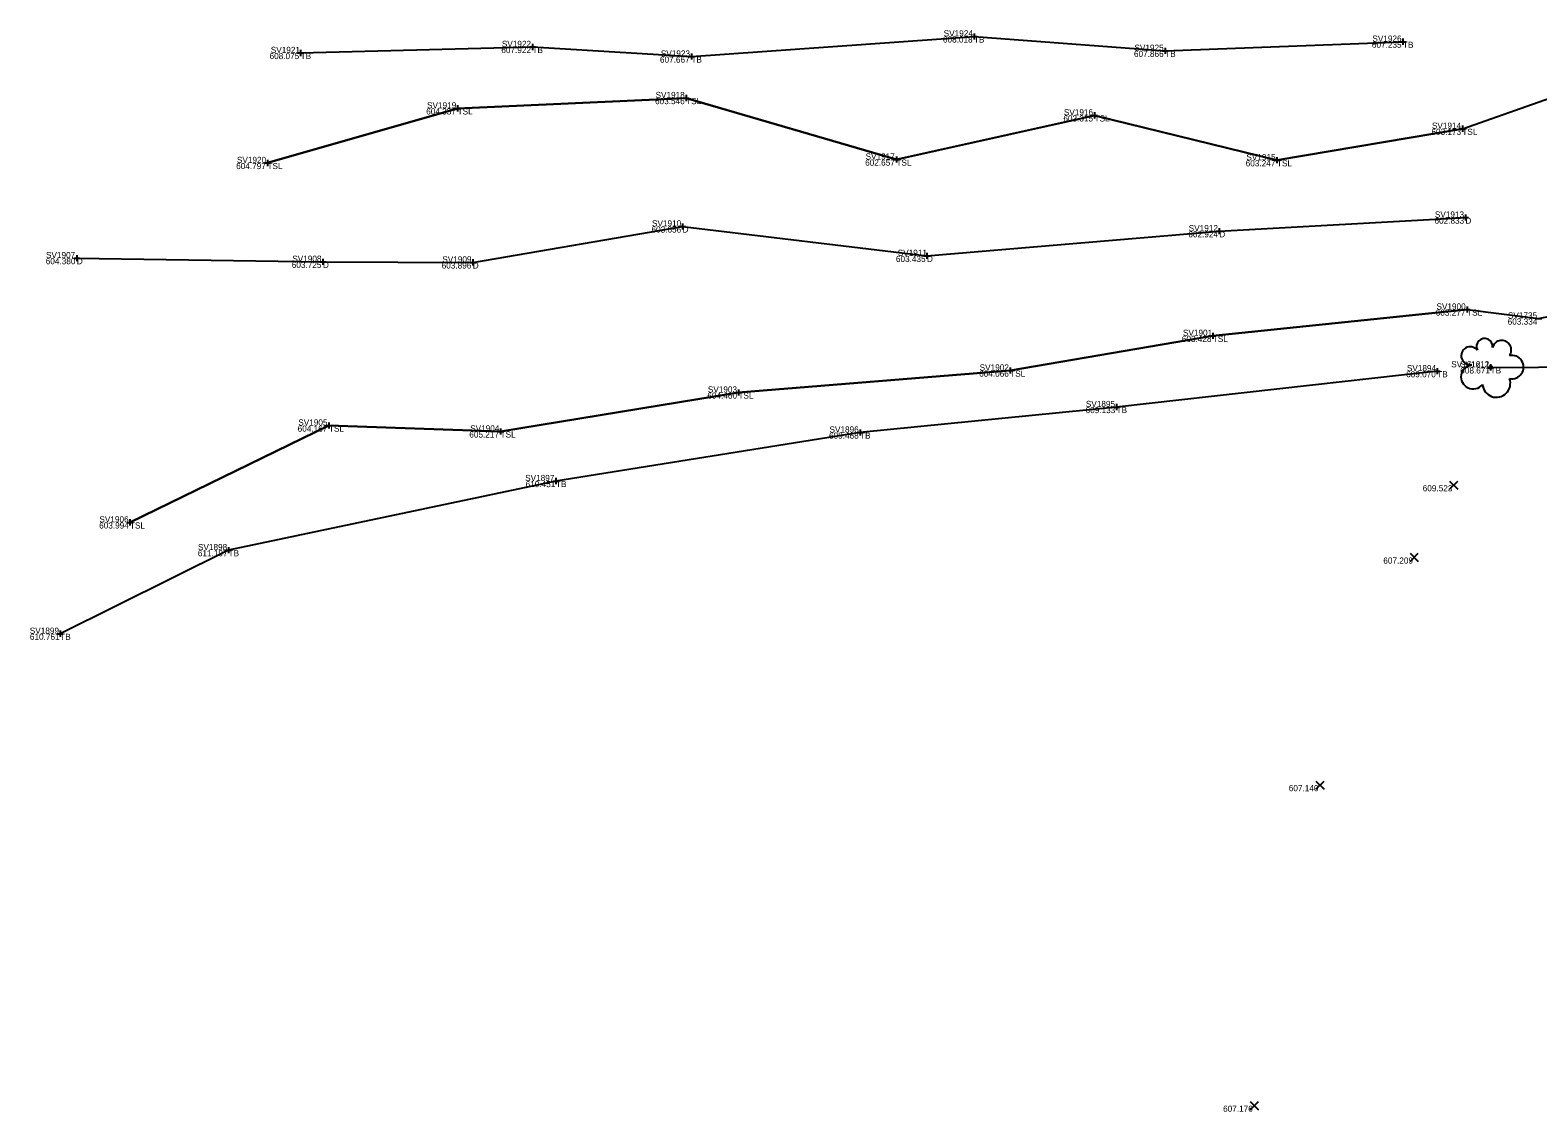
# Model space of a CAD drawing. Extents: x -2 to 1979875, y -2 to 232027.
# Drawn here: x 1978304.6 to 1978427.5, y 231237.5 to 231325.6 of the extents above; entities that cross this region are included whole.
import ezdxf

# ---------------------------------------------------------------- set-up
doc = ezdxf.new("R2010")
doc.units = 0
for name, color, linetype in [('_CIVIL_CONSTRUCTION', 7, 'Continuous'), ('DR_X_Ditch', 7, 'Continuous'), ('GE_X_Alignment', 7, 'Continuous'), ('GE_X_Alignment_100_Curve_Data', 7, 'Continuous'), ('GE_X_Alignment_100_Stations', 7, 'Continuous'), ('HY_X_Water_Edge', 7, 'Continuous'), ('SV_X_Random_Point', 7, 'Continuous'), ('SV_X_Toe_of_Slope', 7, 'Continuous'), ('SV_X_Top_of_Bank', 7, 'Continuous'), ('VG_X_Cells', 7, 'Continuous')]:
    doc.layers.add(name, color=color, linetype=linetype)

msp = doc.modelspace()

# ---------------------------------------------------------------- linework, layer by layer
at = {"layer": 'DR_X_Ditch'}
msp.add_lwpolyline([(1978308.45, 231307), (1978328.5, 231306.7), (1978340.7, 231306.65), (1978357.79, 231309.58), (1978377.7, 231307.18), (1978401.51, 231309.19), (1978421.56, 231310.3)], dxfattribs=at)
at = {"layer": 'GE_X_Alignment_100_Curve_Data'}
for p, q in [((1978381.53, 231325.31), (1978381.53, 231324.81)), ((1978345.31, 231324.2), (1978345.81, 231324.2)), ((1978345.56, 231324.45), (1978345.56, 231323.95)), ((1978345.56, 231324.2), (1978345.56, 231324.2)), ((1978381.28, 231325.06), (1978381.78, 231325.06)), ((1978381.53, 231325.06), (1978381.53, 231325.06)), ((1978397.1, 231324.14), (1978397.1, 231323.64)), ((1978416.22, 231324.63), (1978416.72, 231324.63)), ((1978416.47, 231324.88), (1978416.47, 231324.38)), ((1978416.47, 231324.63), (1978416.47, 231324.63)), ((1978326.43, 231323.71), (1978326.93, 231323.71)), ((1978326.68, 231323.96), (1978326.68, 231323.46)), ((1978326.68, 231323.71), (1978326.68, 231323.71)), ((1978358.26, 231323.42), (1978358.76, 231323.42)), ((1978358.51, 231323.67), (1978358.51, 231323.17)), ((1978358.51, 231323.42), (1978358.51, 231323.42)), ((1978396.85, 231323.89), (1978397.35, 231323.89)), ((1978397.1, 231323.89), (1978397.1, 231323.89)), ((1978339.22, 231319.2), (1978339.72, 231319.2)), ((1978339.47, 231319.45), (1978339.47, 231318.95)), ((1978339.47, 231319.2), (1978339.47, 231319.2)), ((1978357.83, 231320.04), (1978358.33, 231320.04)), ((1978358.08, 231320.29), (1978358.08, 231319.79)), ((1978358.08, 231320.04), (1978358.08, 231320.04)), ((1978391.1, 231318.63), (1978391.6, 231318.63)), ((1978391.35, 231318.88), (1978391.35, 231318.38)), ((1978391.35, 231318.63), (1978391.35, 231318.63)), ((1978421.06, 231317.54), (1978421.56, 231317.54)), ((1978421.31, 231317.79), (1978421.31, 231317.29)), ((1978421.31, 231317.54), (1978421.31, 231317.54)), ((1978323.73, 231314.75), (1978324.23, 231314.75)), ((1978323.98, 231315), (1978323.98, 231314.5)), ((1978323.98, 231314.75), (1978323.98, 231314.75)), ((1978374.96, 231315.03), (1978375.46, 231315.03)), ((1978375.21, 231315.28), (1978375.21, 231314.78)), ((1978375.21, 231315.03), (1978375.21, 231315.03)), ((1978405.96, 231314.97), (1978406.46, 231314.97)), ((1978406.21, 231315.22), (1978406.21, 231314.72)), ((1978406.21, 231314.97), (1978406.21, 231314.97)), ((1978421.56, 231310.55), (1978421.56, 231310.05)), ((1978357.54, 231309.58), (1978358.04, 231309.58)), ((1978357.79, 231309.83), (1978357.79, 231309.33)), ((1978357.79, 231309.58), (1978357.79, 231309.58)), ((1978401.51, 231309.44), (1978401.51, 231308.94)), ((1978421.31, 231310.3), (1978421.81, 231310.3)), ((1978421.56, 231310.3), (1978421.56, 231310.3)), ((1978401.26, 231309.19), (1978401.76, 231309.19)), ((1978401.51, 231309.19), (1978401.51, 231309.19)), ((1978308.2, 231307), (1978308.7, 231307)), ((1978308.45, 231307.25), (1978308.45, 231306.75)), ((1978308.45, 231307), (1978308.45, 231307)), ((1978328.5, 231306.95), (1978328.5, 231306.45)), ((1978340.7, 231306.9), (1978340.7, 231306.4)), ((1978377.45, 231307.18), (1978377.95, 231307.18)), ((1978377.7, 231307.43), (1978377.7, 231306.93)), ((1978377.7, 231307.18), (1978377.7, 231307.18)), ((1978328.25, 231306.7), (1978328.75, 231306.7)), ((1978328.5, 231306.7), (1978328.5, 231306.7)), ((1978340.45, 231306.65), (1978340.95, 231306.65)), ((1978340.7, 231306.65), (1978340.7, 231306.65)), ((1978421.45, 231302.81), (1978421.95, 231302.81)), ((1978421.7, 231303.06), (1978421.7, 231302.56)), ((1978421.7, 231302.81), (1978421.7, 231302.81)), ((1978427.27, 231302.08), (1978427.77, 231302.08)), ((1978400.98, 231300.92), (1978400.98, 231300.42)), ((1978400.73, 231300.67), (1978401.23, 231300.67)), ((1978400.98, 231300.67), (1978400.98, 231300.67)), ((1978423.61, 231298.35), (1978423.61, 231297.85)), ((1978384.23, 231297.84), (1978384.73, 231297.84)), ((1978384.48, 231298.09), (1978384.48, 231297.59)), ((1978384.48, 231297.84), (1978384.48, 231297.84)), ((1978419.01, 231297.79), (1978419.51, 231297.79)), ((1978419.26, 231298.04), (1978419.26, 231297.54)), ((1978419.26, 231297.79), (1978419.26, 231297.79)), ((1978423.36, 231298.1), (1978423.86, 231298.1)), ((1978423.61, 231298.1), (1978423.61, 231298.1)), ((1978362.09, 231296.05), (1978362.59, 231296.05)), ((1978362.34, 231296.3), (1978362.34, 231295.8)), ((1978362.34, 231296.05), (1978362.34, 231296.05)), ((1978392.89, 231294.87), (1978393.39, 231294.87)), ((1978393.14, 231295.12), (1978393.14, 231294.62)), ((1978393.14, 231294.87), (1978393.14, 231294.87)), ((1978328.74, 231293.36), (1978329.24, 231293.36)), ((1978328.99, 231293.61), (1978328.99, 231293.11)), ((1978328.99, 231293.36), (1978328.99, 231293.36)), ((1978342.72, 231292.88), (1978343.22, 231292.88)), ((1978342.97, 231293.13), (1978342.97, 231292.63)), ((1978342.97, 231292.88), (1978342.97, 231292.88)), ((1978372, 231292.79), (1978372.5, 231292.79)), ((1978372.25, 231293.04), (1978372.25, 231292.54)), ((1978372.25, 231292.79), (1978372.25, 231292.79)), ((1978347.23, 231288.84), (1978347.73, 231288.84)), ((1978347.48, 231289.09), (1978347.48, 231288.59)), ((1978347.48, 231288.84), (1978347.48, 231288.84)), ((1978312.53, 231285.47), (1978313.03, 231285.47)), ((1978312.78, 231285.72), (1978312.78, 231285.22)), ((1978312.78, 231285.47), (1978312.78, 231285.47)), ((1978320.56, 231283.21), (1978321.06, 231283.21)), ((1978320.81, 231283.46), (1978320.81, 231282.96)), ((1978320.81, 231283.21), (1978320.81, 231283.21)), ((1978306.85, 231276.4), (1978307.35, 231276.4)), ((1978307.1, 231276.65), (1978307.1, 231276.15)), ((1978307.1, 231276.4), (1978307.1, 231276.4))]:
    msp.add_line(p, q, dxfattribs=at)
at = {"layer": 'HY_X_Water_Edge'}
for points in [[(1978323.98, 231314.75), (1978339.47, 231319.2), (1978358.08, 231320.04), (1978375.21, 231315.03), (1978391.35, 231318.63), (1978406.21, 231314.97), (1978421.31, 231317.54), (1978435.58, 231322.55), (1978449.25, 231320.07), (1978473.82, 231312.81), (1978495.86, 231306.57), (1978508.58, 231305.62), (1978536.74, 231298.05), (1978560.61, 231297.2), (1978586.68, 231285.45), (1978599.48, 231285.01), (1978613.3, 231289.77), (1978626.81, 231296.49), (1978627.99, 231296.51), (1978640.32, 231295.77)], [(1978312.78, 231285.47), (1978328.99, 231293.36), (1978342.97, 231292.88), (1978362.34, 231296.05), (1978384.48, 231297.84), (1978400.98, 231300.67), (1978421.7, 231302.81), (1978427.52, 231302.08), (1978445.61, 231305.74), (1978459.48, 231305.3), (1978473.42, 231300.44), (1978487.7, 231293.26), (1978501.3, 231291.37), (1978535.38, 231278.52), (1978551.52, 231276.84), (1978576.9, 231270.77), (1978597.13, 231271.73), (1978620.91, 231280.58), (1978631.82, 231277.19), (1978672.58, 231269.51)]]:
    msp.add_lwpolyline(points, dxfattribs=at)
at = {"layer": 'SV_X_Random_Point'}
for p, q in [((1978420.27, 231288.17), (1978420.94, 231288.83)), ((1978420.27, 231288.83), (1978420.94, 231288.17)), ((1978417.06, 231282.28), (1978417.72, 231282.95)), ((1978417.06, 231282.95), (1978417.72, 231282.28)), ((1978409.37, 231263.74), (1978410.04, 231264.4)), ((1978409.37, 231264.4), (1978410.04, 231263.74)), ((1978404.02, 231237.62), (1978404.69, 231238.29)), ((1978404.02, 231238.29), (1978404.69, 231237.62))]:
    msp.add_line(p, q, dxfattribs=at)
at = {"layer": 'SV_X_Toe_of_Slope'}
for points in [[(1978421.31, 231317.54), (1978406.21, 231314.97), (1978391.35, 231318.63), (1978375.21, 231315.03), (1978358.08, 231320.04), (1978339.47, 231319.2), (1978323.98, 231314.75)], [(1978421.7, 231302.81), (1978400.98, 231300.67), (1978384.48, 231297.84), (1978362.34, 231296.05), (1978342.97, 231292.88), (1978328.99, 231293.36), (1978312.78, 231285.47)]]:
    msp.add_lwpolyline(points, dxfattribs=at)
at = {"layer": 'SV_X_Top_of_Bank'}
for points in [[(1978326.68, 231323.71), (1978345.56, 231324.2), (1978358.51, 231323.42), (1978381.53, 231325.06), (1978397.1, 231323.89), (1978416.47, 231324.63)], [(1978423.61, 231298.1), (1978447.1, 231298.25), (1978468.31, 231297.35), (1978487.01, 231288.92), (1978500.87, 231282.41), (1978520.98, 231277.41), (1978540.8, 231272.18), (1978564.01, 231269.46), (1978584.6, 231265.4), (1978604.53, 231264)], [(1978419.26, 231297.79), (1978393.14, 231294.87), (1978372.25, 231292.79), (1978347.48, 231288.84), (1978320.81, 231283.21), (1978307.1, 231276.4)]]:
    msp.add_lwpolyline(points, dxfattribs=at)
at = {"layer": 'VG_X_Cells'}
msp.add_circle((1978423.61, 231298.1), 0.12, dxfattribs=at)
for centre, radius, start, end in [((1978421.95, 231299.04), 0.735, 39.0625, 279.5412), ((1978423.12, 231299.79), 0.658, 354.0047, 205.9741), ((1978424.52, 231299.52), 0.776, 323.83, 165.0376), ((1978422.18, 231297.33), 0.987, 96.1722, 320.5737), ((1978425.34, 231298.12), 0.957, 259.1453, 101.4596), ((1978424.08, 231296.8), 1.14, 184.9476, 19.4572)]:
    msp.add_arc(centre, radius, start, end, dxfattribs=at)

# ---------------------------------------------------------------- texts
at = {"layer": '_CIVIL_CONSTRUCTION'}
for s, p in [('607.922', (1978343.03, 231323.7)), ('608.018', (1978379, 231324.56)), ('607.235', (1978413.94, 231324.13)), ('608.075', (1978324.15, 231323.21)), ('607.667', (1978355.95, 231322.92)), ('607.866', (1978394.56, 231323.39)), ('604.337', (1978336.91, 231318.7)), ('603.546', (1978355.55, 231319.54)), ('603.315', (1978388.81, 231318.13)), ('603.173', (1978418.79, 231317.04)), ('604.797', (1978321.43, 231314.25)), ('602.657', (1978372.66, 231314.53)), ('603.247', (1978403.66, 231314.47)), ('603.656', (1978355.26, 231309.08)), ('602.833', (1978419.04, 231309.8)), ('602.924', (1978398.99, 231308.69)), ('604.380', (1978305.92, 231306.5)), ('603.435', (1978375.17, 231306.68)), ('603.725', (1978325.96, 231306.2)), ('603.896', (1978338.17, 231306.15)), ('603.277', (1978419.14, 231302.31)), ('603.334', (1978425, 231301.58)), ('603.428', (1978398.46, 231300.17)), ('604.066', (1978381.95, 231297.34)), ('609.070', (1978416.73, 231297.29)), ('608.671', (1978421.14, 231297.6)), ('608.671', (1978421.14, 231297.6)), ('604.460', (1978359.81, 231295.55)), ('609.133', (1978390.62, 231294.37)), ('604.167', (1978326.44, 231292.86)), ('605.217', (1978340.42, 231292.38)), ('609.468', (1978369.72, 231292.29)), ('610.451', (1978345.01, 231288.34)), ('609.523', (1978418.08, 231288)), ('603.994', (1978310.27, 231284.97)), ('611.197', (1978318.31, 231282.71)), ('607.209', (1978414.87, 231282.11)), ('610.761', (1978304.63, 231275.9)), ('607.140', (1978407.17, 231263.57)), ('607.176', (1978401.82, 231237.46))]:
    msp.add_text(s, height=0.5, dxfattribs=at).set_placement(p)
at = {"layer": 'GE_X_Alignment'}
for s, p in [('SV1924', (1978379.06, 231325.06)), ('SV1921', (1978324.25, 231323.71)), ('SV1922', (1978343.07, 231324.2)), ('SV1925', (1978394.6, 231323.89)), ('SV1926', (1978413.98, 231324.63)), ('SV1923', (1978356.02, 231323.42)), ('SV1918', (1978355.59, 231320.04)), ('SV1919', (1978336.98, 231319.2)), ('SV1916', (1978388.85, 231318.63)), ('SV1914', (1978418.83, 231317.54)), ('SV1917', (1978372.7, 231315.03)), ('SV1915', (1978403.72, 231314.97)), ('SV1920', (1978321.49, 231314.75)), ('SV1913', (1978419.07, 231310.3)), ('SV1910', (1978355.3, 231309.58)), ('SV1912', (1978399.02, 231309.19)), ('SV1907', (1978305.94, 231307)), ('SV1908', (1978326, 231306.7)), ('SV1909', (1978338.22, 231306.65)), ('SV1911', (1978375.32, 231307.18)), ('SV1900', (1978419.2, 231302.81)), ('SV1735', (1978425.02, 231302.08)), ('SV1901', (1978398.55, 231300.67)), ('SV1902', (1978381.99, 231297.84)), ('SV1894', (1978416.79, 231297.79)), ('SV1612_1', (1978420.4, 231298.1)), ('SV1612', (1978421.12, 231298.1)), ('SV1903', (1978359.85, 231296.05)), ('SV1895', (1978390.64, 231294.87)), ('SV1905', (1978326.49, 231293.36)), ('SV1904', (1978340.49, 231292.88)), ('SV1896', (1978369.76, 231292.79)), ('SV1897', (1978344.97, 231288.84)), ('SV1906', (1978310.29, 231285.47)), ('SV1898', (1978318.32, 231283.21)), ('SV1899', (1978304.62, 231276.4))]:
    msp.add_text(s, height=0.5, dxfattribs=at).set_placement(p)
at = {"layer": 'GE_X_Alignment_100_Stations'}
for s, p in [('TB', (1978345.56, 231323.7)), ('TB', (1978381.53, 231324.56)), ('TB', (1978416.47, 231324.13)), ('TB', (1978326.68, 231323.21)), ('TB', (1978358.51, 231322.92)), ('TB', (1978397.1, 231323.39)), ('TSL', (1978339.47, 231318.7)), ('TSL', (1978358.08, 231319.54)), ('TSL', (1978391.35, 231318.13)), ('TSL', (1978421.31, 231317.04)), ('TSL', (1978323.98, 231314.25)), ('TSL', (1978375.21, 231314.53)), ('TSL', (1978406.21, 231314.47)), ('D', (1978357.79, 231309.08)), ('D', (1978421.56, 231309.8)), ('D', (1978401.51, 231308.69)), ('D', (1978308.45, 231306.5)), ('D', (1978377.7, 231306.68)), ('D', (1978328.5, 231306.2)), ('D', (1978340.7, 231306.15)), ('TSL', (1978421.7, 231302.31)), ('TSL', (1978400.98, 231300.17)), ('TSL', (1978384.48, 231297.34)), ('TB', (1978419.26, 231297.29)), ('TB', (1978423.61, 231297.6)), ('T', (1978423.61, 231297.6)), ('TSL', (1978362.34, 231295.55)), ('TB', (1978393.14, 231294.37)), ('TSL', (1978328.99, 231292.86)), ('TSL', (1978342.97, 231292.38)), ('TB', (1978372.25, 231292.29)), ('TB', (1978347.48, 231288.34)), ('TSL', (1978312.78, 231284.97)), ('TB', (1978320.81, 231282.71)), ('TB', (1978307.1, 231275.9))]:
    msp.add_text(s, height=0.5, dxfattribs=at).set_placement(p)

doc.saveas('drawing.dxf')
